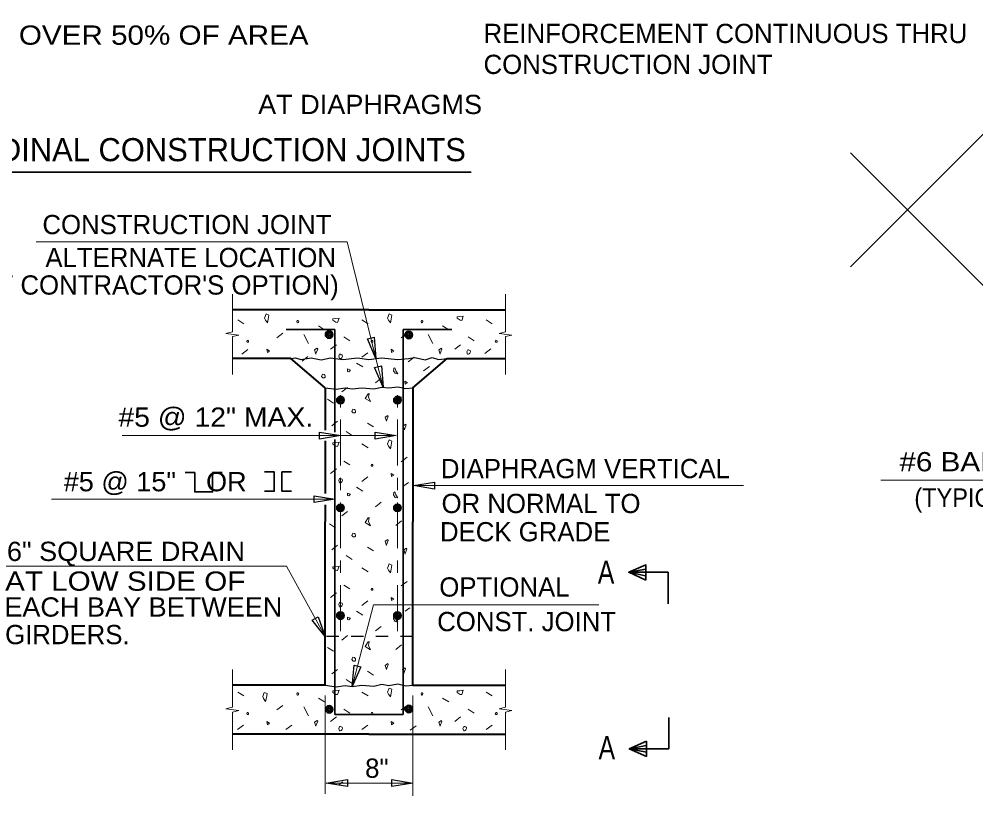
# Model space of a CAD drawing. Extents: x 0 to 34, y 0 to 23.4.
# Drawn here: x 16.45 to 24.21, y 9.27 to 15.58 of the extents above; entities that cross this region are included whole.
import ezdxf
from ezdxf.enums import TextEntityAlignment as Align

# ---------------------------------------------------------------- set-up
doc = ezdxf.new("R2010")
doc.units = 0
doc.header["$LTSCALE"] = 0.062
doc.linetypes.add('LONG_DASH_SHORT_DASH', pattern=[9.9, 6, -1.2, 1.5, -1.2])
doc.linetypes.add('SHORT_DASHED', pattern=[2.7, 1.5, -1.2])
for name, color, linetype, lineweight in [('1', 7, 'Continuous', 40), ('2', 7, 'SHORT_DASHED', 13), ('3', 7, 'Continuous', 35), ('4', 7, 'Continuous', 13), ('5', 7, 'LONG_DASH_SHORT_DASH', 13), ('7', 7, 'Continuous', 13)]:
    doc.layers.add(name, color=color, linetype=linetype, lineweight=lineweight)

msp = doc.modelspace()

# ---------------------------------------------------------------- linework, layer by layer
at = {"layer": '1', "lineweight": 13}
for p, q in [((18.1801, 13.03943), (18.1801, 13.34542)), ((20.39677, 13.03943), (20.39677, 13.34542)), ((18.1801, 12.69438), (18.1801, 13.00036)), ((20.39677, 12.69438), (20.39677, 13.00036)), ((18.1801, 9.99151), (18.1801, 10.2975)), ((20.39677, 9.99151), (20.39677, 10.2975)), ((18.1801, 9.64646), (18.1801, 9.95245)), ((20.39677, 9.64646), (20.39677, 9.95245))]:
    msp.add_line(p, q, dxfattribs=at)
at = {"layer": '1'}
for p, q in [((19.28844, 13.21781), (18.1801, 13.21781)), ((19.28844, 13.21781), (20.39677, 13.21781)), ((19.64469, 12.58448), (19.92177, 12.82198)), ((19.92177, 12.82198), (20.39677, 12.82198)), ((18.93219, 12.58448), (18.93219, 12.24099)), ((19.64469, 12.58448), (19.64469, 11.49594)), ((18.93219, 12.15427), (18.93219, 11.72719)), ((18.93219, 11.63474), (18.93219, 11.49594)), ((18.93219, 10.1699), (18.93219, 11.49594)), ((19.64469, 10.1699), (19.64469, 11.49594)), ((18.93219, 10.1699), (18.1801, 10.1699)), ((19.64469, 10.1699), (20.39677, 10.1699)), ((19.28844, 9.77406), (18.1801, 9.77406)), ((19.28844, 9.77406), (20.39677, 9.77406))]:
    msp.add_line(p, q, dxfattribs=at)
at = {"layer": '1', "lineweight": 13}
for points in [[(18.1801, 13.03943), (18.12802, 13.02641), (18.23219, 13.01339), (18.1801, 13.00036)], [(20.39677, 13.03943), (20.34469, 13.02641), (20.44885, 13.01339), (20.39677, 13.00036)], [(18.1801, 9.99151), (18.12802, 9.97849), (18.23219, 9.96547), (18.1801, 9.95245)], [(20.39677, 9.99151), (20.34469, 9.97849), (20.44885, 9.96547), (20.39677, 9.95245)]]:
    msp.add_lwpolyline(points, dxfattribs=at)
at = {"layer": '1'}
msp.add_lwpolyline([(18.93219, 12.58448), (18.6551, 12.82198), (18.1801, 12.82198)], dxfattribs=at)
at = {"layer": '1', "lineweight": 25}
for points in [[(18.6551, 12.82198), (18.69344, 12.82786), (18.73573, 12.81599), (18.81865, 12.82974), (18.90161, 12.81141), (18.97646, 12.82786), (19.07568, 12.81505), (19.19604, 12.82786), (19.28708, 12.81599), (19.3912, 12.8288), (19.52297, 12.81411), (19.60958, 12.82406), (19.6612, 12.83156), (19.74578, 12.81234), (19.80109, 12.83063), (19.85313, 12.81599), (19.92177, 12.82198)], [(18.93219, 12.58448), (19.02354, 12.57484), (19.09568, 12.58385), (19.15313, 12.57693), (19.23182, 12.58526), (19.32859, 12.5776), (19.39255, 12.59146), (19.45, 12.58385), (19.52214, 12.59427), (19.58776, 12.58036), (19.64469, 12.58448)], [(18.93219, 10.1699), (19.02354, 10.15849), (19.09568, 10.16917), (19.15313, 10.16094), (19.23182, 10.17078), (19.32859, 10.16177), (19.39255, 10.17818), (19.45, 10.16917), (19.52214, 10.18146), (19.58776, 10.16505), (19.64469, 10.1699)]]:
    msp.add_lwpolyline(points, dxfattribs=at)
at = {"layer": '2', "lineweight": 25}
msp.add_line((19.64469, 10.56573), (18.93219, 10.56573), dxfattribs=at)
at = {"layer": '3'}
for p, q in [((23.19479, 13.56807), (26.3226, 16.69589)), ((26.3226, 11.36385), (23.19479, 14.49167)), ((18.61552, 13.05948), (19.01135, 13.05948)), ((19.01135, 13.05948), (19.01135, 12.22406)), ((19.56552, 13.05948), (19.96135, 13.05948)), ((19.56552, 13.05948), (19.56552, 9.9324)), ((19.01135, 12.16604), (19.01135, 9.9324)), ((19.01135, 9.9324), (19.56552, 9.9324))]:
    msp.add_line(p, q, dxfattribs=at)
for points in [[(17.79656, 11.89714), (17.87531, 11.89714), (17.87531, 11.73953), (18.01974, 11.73953), (18.01974, 11.89714), (18.09854, 11.89714)], [(18.44172, 11.90266), (18.52047, 11.90266), (18.52047, 11.74505), (18.44172, 11.74505)], [(18.6612, 11.74505), (18.58245, 11.74505), (18.58245, 11.90266), (18.6612, 11.90266)]]:
    msp.add_lwpolyline(points, dxfattribs=at)
for centre, radius in [((18.96511, 13.01713), 0.03048), ((19.61092, 13.01431), 0.03048), ((18.96511, 13.01713), 0.02032), ((18.96511, 13.01713), 0.01016), ((19.61092, 13.01431), 0.02032), ((19.61092, 13.01431), 0.01016), ((19.0572, 12.4855), 0.03048), ((19.0572, 12.4855), 0.02032), ((19.51971, 12.48553), 0.03048), ((19.51971, 12.48553), 0.02032), ((19.0572, 12.4855), 0.01016), ((19.51971, 12.48553), 0.01016), ((19.05716, 11.61053), 0.03048), ((19.05716, 11.61053), 0.02032), ((19.05716, 11.61053), 0.01016), ((19.51971, 11.61053), 0.03048), ((19.51971, 11.61053), 0.02032), ((19.51971, 11.61053), 0.01016), ((19.05717, 10.7355), 0.03048), ((19.05717, 10.7355), 0.02032), ((19.05717, 10.7355), 0.01016), ((19.51969, 10.7355), 0.03048), ((19.51969, 10.7355), 0.02032), ((19.51969, 10.7355), 0.01016), ((18.96511, 9.97472), 0.03048), ((18.96511, 9.97472), 0.02032), ((18.96511, 9.97472), 0.01016), ((19.61092, 9.97754), 0.03048), ((19.61092, 9.97754), 0.02032), ((19.61092, 9.97754), 0.01016)]:
    msp.add_circle(centre, radius, dxfattribs=at)
at = {"layer": '4', "lineweight": 35}
for p, q in [((15.0951, 14.3362), (20.11854, 14.3362)), ((21.39667, 11.08708), (21.53594, 11.11286)), ((21.39667, 11.08708), (21.53297, 11.05745)), ((21.71667, 11.08708), (21.71667, 10.83109)), ((21.72052, 9.65281), (21.72052, 9.9088)), ((21.40052, 9.65281), (21.53682, 9.68245)), ((21.40052, 9.65281), (21.53979, 9.62703))]:
    msp.add_line(p, q, dxfattribs=at)
at = {"layer": '4'}
for p, q in [((16.58875, 13.77057), (19.11203, 13.77057)), ((19.11203, 13.77057), (19.34531, 12.82318)), ((19.34531, 12.82318), (19.40271, 12.5901)), ((17.28469, 12.19688), (19.05891, 12.19688)), ((19.05891, 12.19688), (19.50948, 12.19688)), ((19.43802, 12.20599), (19.45922, 12.18833)), ((19.65031, 11.79109), (22.32781, 11.79109)), ((16.71297, 11.68135), (19.01135, 11.68135)), ((19.32406, 10.82224), (19.15182, 10.16115)), ((19.32406, 10.82224), (21.1538, 10.82224)), ((18.93219, 10.0863), (18.93219, 9.28776)), ((19.64469, 10.0863), (19.64469, 9.27219)), ((18.94208, 9.37641), (19.64469, 9.37641)), ((19.07594, 9.38693), (19.04057, 9.35865))]:
    msp.add_line(p, q, dxfattribs=at)
at = {"layer": '4', "lineweight": 25}
for points in [[(19.27547, 12.98333), (19.33078, 12.99698), (19.34401, 12.82411)], [(19.33417, 12.74932), (19.38948, 12.76297), (19.40271, 12.5901)], [(18.88792, 12.16839), (18.88792, 12.22536), (19.05891, 12.19688)], [(19.33849, 12.16839), (19.33849, 12.22536), (19.50948, 12.19688)], [(19.8213, 11.81958), (19.8213, 11.7626), (19.65031, 11.79109)], [(18.84438, 11.65354), (18.84438, 11.70917), (19.01135, 11.68135)], [(18.82771, 10.69891), (18.87656, 10.72563), (18.93219, 10.56573)], [(19.16734, 10.3338), (19.22255, 10.31943), (19.15182, 10.16115)], [(19.11307, 9.4049), (19.11307, 9.34792), (18.94208, 9.37641)], [(19.4737, 9.34792), (19.4737, 9.4049), (19.64469, 9.37641)]]:
    msp.add_lwpolyline(points, close=True, dxfattribs=at)
at = {"layer": '4'}
for points in [[(14.30089, 12.47807), (16.32745, 11.13833), (18.61932, 11.13833), (18.93219, 10.56573)], [(23.44297, 11.83401), (25.27693, 11.83401), (25.55833, 12.11911)]]:
    msp.add_lwpolyline(points, dxfattribs=at)
at = {"layer": '4', "lineweight": 35}
for points in [[(21.39667, 11.08708), (21.53526, 11.14719), (21.53526, 11.02307)], [(21.71667, 11.08708), (21.39667, 11.08708), (21.53526, 11.02307)], [(21.72052, 9.65281), (21.40052, 9.65281), (21.53911, 9.71682)], [(21.40052, 9.65281), (21.53911, 9.59271), (21.53911, 9.71682)]]:
    msp.add_lwpolyline(points, dxfattribs=at)
at = {"layer": '5'}
for p, q in [((19.05719, 10.61052), (19.05719, 12.56885)), ((19.51969, 10.61052), (19.51969, 12.56885))]:
    msp.add_line(p, q, dxfattribs=at)
at = {"layer": '7'}
for p, q in [((18.22323, 13.13714), (18.27266, 13.10583)), ((19.23161, 13.13714), (19.28104, 13.10583)), ((20.24, 13.13714), (20.28943, 13.10583)), ((18.87792, 13.08807), (18.9274, 13.05682)), ((19.8863, 13.08807), (19.93578, 13.05682)), ((18.58885, 13.02839), (18.54073, 12.99177)), ((18.76042, 13.01729), (18.79708, 12.94375)), ((19.08427, 12.99776), (19.13375, 12.96651)), ((19.59724, 13.02839), (19.54911, 12.99177)), ((19.7688, 13.01729), (19.80547, 12.94375)), ((20.09266, 12.99776), (20.14214, 12.96651)), ((18.30599, 12.89531), (18.25786, 12.8587)), ((19.0238, 12.93464), (18.97568, 12.89802)), ((20.03219, 12.93464), (19.98406, 12.89802)), ((20.27656, 12.90042), (20.22844, 12.8638)), ((18.79359, 12.8388), (18.74547, 12.80219)), ((19.27844, 12.86964), (19.23031, 12.83302)), ((19.65557, 12.83271), (19.60745, 12.79609)), ((19.18849, 12.78568), (19.23797, 12.75443)), ((19.77984, 12.75875), (19.73172, 12.72214)), ((19.38875, 12.66318), (19.34063, 12.62656)), ((19.11521, 12.58849), (19.06708, 12.55188)), ((19.5538, 12.51203), (19.50568, 12.47542)), ((18.95219, 12.4924), (19.00172, 12.4612)), ((19.03411, 12.31375), (18.98599, 12.27714)), ((19.27656, 12.2988), (19.32599, 12.26776)), ((19.10302, 12.23052), (19.15255, 12.19927)), ((19.23161, 12.12979), (19.28104, 12.09849)), ((19.08427, 11.99042), (19.13375, 11.95917)), ((19.59724, 12.02104), (19.54911, 11.98443)), ((19.0238, 11.92729), (18.97568, 11.89068)), ((19.27844, 11.86229), (19.23031, 11.82568)), ((19.6088, 11.81708), (19.57156, 11.78875)), ((19.18849, 11.77833), (19.23797, 11.74708)), ((19.38875, 11.65583), (19.34063, 11.61922)), ((19.11521, 11.58115), (19.06708, 11.54453)), ((19.5538, 11.50469), (19.50568, 11.46807)), ((18.96755, 11.4799), (19.01708, 11.4487)), ((19.03411, 11.30641), (18.98599, 11.26979)), ((19.27656, 11.29146), (19.32599, 11.26042)), ((19.10302, 11.22318), (19.15255, 11.19193)), ((19.23161, 11.12245), (19.28104, 11.09115)), ((19.08427, 10.98307), (19.13375, 10.95182)), ((19.59724, 11.0137), (19.54911, 10.97708)), ((19.0238, 10.91995), (18.97568, 10.88333)), ((19.27844, 10.85495), (19.23031, 10.81833)), ((19.61901, 10.79943), (19.58177, 10.77109)), ((19.18849, 10.77099), (19.23797, 10.73974)), ((19.38875, 10.64849), (19.34063, 10.61188)), ((19.11521, 10.5738), (19.06708, 10.53719)), ((19.5538, 10.49734), (19.50568, 10.46073)), ((18.95219, 10.47771), (19.00172, 10.44651)), ((19.03411, 10.29906), (18.98599, 10.26245)), ((19.27656, 10.28411), (19.32599, 10.25307)), ((19.10302, 10.21583), (19.15255, 10.18458)), ((18.22323, 10.1151), (18.27266, 10.0838)), ((19.23161, 10.1151), (19.28104, 10.0838)), ((20.24, 10.1151), (20.28943, 10.0838)), ((18.87792, 10.06604), (18.9274, 10.03479)), ((19.8863, 10.06604), (19.93578, 10.03479)), ((18.58885, 10.00635), (18.54073, 9.96974)), ((18.76042, 9.99526), (18.79708, 9.92172)), ((19.08427, 9.97573), (19.13375, 9.94448)), ((19.59724, 10.00635), (19.54911, 9.96974)), ((19.7688, 9.99526), (19.80547, 9.92172)), ((20.09266, 9.97573), (20.14214, 9.94448)), ((19.0238, 9.9126), (18.97568, 9.87599)), ((20.03219, 9.9126), (19.98406, 9.87599)), ((18.27005, 9.8476), (18.22193, 9.81099)), ((18.6626, 9.84661), (18.61448, 9.81)), ((19.27844, 9.8476), (19.23031, 9.81099)), ((19.67099, 9.84151), (19.62286, 9.8049)), ((20.28682, 9.8476), (20.2387, 9.81099))]:
    msp.add_line(p, q, dxfattribs=at)
for points in [[(18.45328, 13.18495), (18.44208, 13.15182), (18.44776, 13.13526), (18.46432, 13.11313), (18.47167, 13.1426), (18.47719, 13.17578)], [(18.70344, 13.12229), (18.70635, 13.11307), (18.70901, 13.11307), (18.71276, 13.11401), (18.71547, 13.11667), (18.71813, 13.12229), (18.7174, 13.12781), (18.71276, 13.12875), (18.71078, 13.13068), (18.70714, 13.13068)], [(19.01766, 13.1476), (18.99557, 13.14573), (18.99557, 13.13469), (19.01953, 13.11818), (19.0325, 13.1163), (19.04542, 13.15125)], [(19.45141, 13.1849), (19.44021, 13.15177), (19.44589, 13.13521), (19.46245, 13.11307), (19.46979, 13.14255), (19.47531, 13.17573)], [(19.71182, 13.12229), (19.71474, 13.11307), (19.7174, 13.11307), (19.72115, 13.11401), (19.72385, 13.11667), (19.72651, 13.12229), (19.72578, 13.12781), (19.72115, 13.12875), (19.71917, 13.13068), (19.71552, 13.13068)], [(20.02604, 13.16302), (20.00396, 13.16115), (20.00396, 13.1501), (20.02792, 13.13359), (20.04089, 13.13172), (20.0538, 13.16667)], [(18.30151, 12.97167), (18.29688, 12.96151), (18.30229, 12.95589), (18.30891, 12.95589), (18.31161, 12.95885), (18.31161, 12.96427), (18.31073, 12.96693), (18.30786, 12.9699)], [(19.3099, 12.97167), (19.30526, 12.96151), (19.31068, 12.95589), (19.31729, 12.95589), (19.32, 12.95885), (19.32, 12.96427), (19.31911, 12.96693), (19.31625, 12.9699)], [(20.31828, 12.97167), (20.31365, 12.96151), (20.31906, 12.95589), (20.32568, 12.95589), (20.32839, 12.95885), (20.32839, 12.96427), (20.3275, 12.96693), (20.32464, 12.9699)], [(18.46042, 12.89792), (18.46411, 12.87208), (18.4826, 12.88318)], [(18.84646, 12.8925), (18.85786, 12.85927), (18.85786, 12.86286), (18.87255, 12.89984), (18.8688, 12.90719)], [(19.4688, 12.89792), (19.4725, 12.87208), (19.49099, 12.88318)], [(19.85484, 12.8925), (19.86625, 12.85927), (19.86625, 12.86286), (19.88094, 12.89984), (19.87719, 12.90719)], [(20.08224, 12.87672), (20.08807, 12.85828), (20.09339, 12.85828), (20.10089, 12.8601), (20.1063, 12.86547), (20.11167, 12.87672), (20.11016, 12.88766), (20.10089, 12.88958), (20.09698, 12.89339), (20.08964, 12.89339)], [(19.04307, 12.84078), (19.04891, 12.82234), (19.05422, 12.82234), (19.06172, 12.82417), (19.06714, 12.82953), (19.0725, 12.84078), (19.07099, 12.85172), (19.06172, 12.85365), (19.05781, 12.85745), (19.05047, 12.85745)], [(19.11479, 12.73833), (19.11391, 12.71854), (19.12583, 12.71578), (19.13734, 12.72911)], [(19.49125, 12.7438), (19.48719, 12.72307), (19.50094, 12.70276), (19.52396, 12.69823), (19.50557, 12.7226), (19.49771, 12.74792)], [(18.91182, 12.69672), (18.90255, 12.67651), (18.91339, 12.66526), (18.92661, 12.66526), (18.93203, 12.67115), (18.93203, 12.68193), (18.93021, 12.68724), (18.92448, 12.69318)], [(19.57896, 12.63964), (19.58266, 12.6138), (19.60115, 12.6249)], [(19.28214, 12.53745), (19.25641, 12.49891), (19.29969, 12.47297), (19.28391, 12.50802), (19.29057, 12.5401)], [(19.15786, 12.41297), (19.14859, 12.39276), (19.15943, 12.38151), (19.17266, 12.38151), (19.17807, 12.3874), (19.17807, 12.39818), (19.17625, 12.40349), (19.17052, 12.40943)], [(19.41906, 12.34656), (19.43042, 12.31333), (19.43042, 12.31688), (19.44521, 12.35391), (19.44146, 12.36125)], [(19.56505, 12.27583), (19.57646, 12.24266), (19.57646, 12.2462), (19.59115, 12.28323), (19.5874, 12.29057)], [(19.01766, 12.14026), (18.99557, 12.13839), (18.99557, 12.12734), (19.01953, 12.11083), (19.0325, 12.10896), (19.04542, 12.14391)], [(19.45141, 12.16219), (19.44021, 12.12906), (19.44589, 12.1125), (19.46245, 12.09036), (19.46979, 12.11984), (19.47531, 12.15302)], [(19.3099, 11.96432), (19.30526, 11.95417), (19.31068, 11.94854), (19.31729, 11.94854), (19.32, 11.95151), (19.32, 11.95693), (19.31911, 11.95958), (19.31625, 11.96255)], [(19.4688, 11.89057), (19.4725, 11.86474), (19.49099, 11.87583)], [(19.04307, 11.83344), (19.04891, 11.815), (19.05422, 11.815), (19.06172, 11.81682), (19.06714, 11.82219), (19.0725, 11.83344), (19.07099, 11.84438), (19.06172, 11.8463), (19.05781, 11.8501), (19.05047, 11.8501)], [(19.11479, 11.73099), (19.11391, 11.7112), (19.12583, 11.70844), (19.13734, 11.72177)], [(19.49125, 11.73646), (19.48719, 11.71573), (19.50094, 11.69542), (19.52396, 11.69089), (19.50557, 11.71526), (19.49771, 11.74057)], [(19.28214, 11.5301), (19.25641, 11.49156), (19.29969, 11.46563), (19.28391, 11.50068), (19.29057, 11.53276)], [(19.15786, 11.40563), (19.14859, 11.38542), (19.15943, 11.37417), (19.17266, 11.37417), (19.17807, 11.38005), (19.17807, 11.39083), (19.17625, 11.39615), (19.17052, 11.40208)], [(19.41906, 11.33922), (19.43042, 11.30599), (19.43042, 11.30953), (19.44521, 11.34656), (19.44146, 11.35391)], [(19.57021, 11.26849), (19.58161, 11.23531), (19.58161, 11.23885), (19.5963, 11.27589), (19.59255, 11.28323)], [(19.01766, 11.13292), (18.99557, 11.13104), (18.99557, 11.12), (19.01953, 11.10349), (19.0325, 11.10161), (19.04542, 11.13656)], [(19.45141, 11.15484), (19.44021, 11.12172), (19.44589, 11.10516), (19.46245, 11.08302), (19.46979, 11.1125), (19.47531, 11.14568)], [(19.3099, 10.95698), (19.30526, 10.94682), (19.31068, 10.9412), (19.31729, 10.9412), (19.32, 10.94417), (19.32, 10.94958), (19.31911, 10.95224), (19.31625, 10.95521)], [(19.4688, 10.88323), (19.4725, 10.8574), (19.49099, 10.86849)], [(19.04307, 10.82609), (19.04891, 10.80766), (19.05422, 10.80766), (19.06172, 10.80948), (19.06714, 10.81484), (19.0725, 10.82609), (19.07099, 10.83703), (19.06172, 10.83896), (19.05781, 10.84276), (19.05047, 10.84276)], [(19.11479, 10.72365), (19.11391, 10.70385), (19.12583, 10.70109), (19.13734, 10.71443)], [(19.49125, 10.72911), (19.48719, 10.70839), (19.50094, 10.68807), (19.52396, 10.68354), (19.50557, 10.70792), (19.49771, 10.73323)], [(19.28214, 10.52276), (19.25641, 10.48422), (19.29969, 10.45828), (19.28391, 10.49333), (19.29057, 10.52542)], [(19.15786, 10.39828), (19.14859, 10.37807), (19.15943, 10.36682), (19.17266, 10.36682), (19.17807, 10.37271), (19.17807, 10.38349), (19.17625, 10.3888), (19.17052, 10.39474)], [(19.41906, 10.33188), (19.43042, 10.29865), (19.43042, 10.30219), (19.44521, 10.33922), (19.44146, 10.34656)], [(19.5599, 10.29708), (19.5713, 10.26391), (19.5713, 10.26745), (19.58599, 10.30448), (19.58224, 10.31182)], [(18.43792, 10.11156), (18.42672, 10.07844), (18.4324, 10.06188), (18.44896, 10.03974), (18.4563, 10.06922), (18.46182, 10.1024)], [(18.70344, 10.10026), (18.70635, 10.09104), (18.70901, 10.09104), (18.71276, 10.09198), (18.71547, 10.09464), (18.71813, 10.10026), (18.7174, 10.10578), (18.71276, 10.10672), (18.71078, 10.10865), (18.70714, 10.10865)], [(19.01766, 10.12557), (18.99557, 10.1237), (18.99557, 10.11266), (19.01953, 10.09615), (19.0325, 10.09427), (19.04542, 10.12922)], [(19.45141, 10.1475), (19.44021, 10.11438), (19.44589, 10.09781), (19.46245, 10.07568), (19.46979, 10.10516), (19.47531, 10.13833)], [(19.71182, 10.10026), (19.71474, 10.09104), (19.7174, 10.09104), (19.72115, 10.09198), (19.72385, 10.09464), (19.72651, 10.10026), (19.72578, 10.10578), (19.72115, 10.10672), (19.71917, 10.10865), (19.71552, 10.10865)], [(20.02604, 10.12557), (20.00396, 10.1237), (20.00396, 10.11266), (20.02792, 10.09615), (20.04089, 10.09427), (20.0538, 10.12922)], [(18.30151, 9.94964), (18.29688, 9.93948), (18.30229, 9.93385), (18.30891, 9.93385), (18.31161, 9.93682), (18.31161, 9.94224), (18.31073, 9.9449), (18.30786, 9.94786)], [(19.3099, 9.94964), (19.30526, 9.93948), (19.31068, 9.93385), (19.31729, 9.93385), (19.32, 9.93682), (19.32, 9.94224), (19.31911, 9.9449), (19.31625, 9.94786)], [(20.31828, 9.94964), (20.31365, 9.93948), (20.31906, 9.93385), (20.32568, 9.93385), (20.32839, 9.93682), (20.32839, 9.94224), (20.3275, 9.9449), (20.32464, 9.94786)], [(18.46042, 9.87589), (18.46411, 9.85005), (18.4826, 9.86115)], [(18.84646, 9.87047), (18.85786, 9.83724), (18.85786, 9.84083), (18.87255, 9.87781), (18.8688, 9.88516)], [(19.4688, 9.87589), (19.4725, 9.85005), (19.49099, 9.86115)], [(19.85484, 9.87047), (19.86625, 9.83724), (19.86625, 9.84083), (19.88094, 9.87781), (19.87719, 9.88516)], [(19.04307, 9.81875), (19.04891, 9.80031), (19.05422, 9.80031), (19.06172, 9.80214), (19.06714, 9.8075), (19.0725, 9.81875), (19.07099, 9.82969), (19.06172, 9.83161), (19.05781, 9.83542), (19.05047, 9.83542)], [(20.05146, 9.81875), (20.05729, 9.80031), (20.0626, 9.80031), (20.0701, 9.80214), (20.07552, 9.8075), (20.08089, 9.81875), (20.07938, 9.82969), (20.0701, 9.83161), (20.0662, 9.83542), (20.05885, 9.83542)]]:
    msp.add_lwpolyline(points, close=True, dxfattribs=at)

# ---------------------------------------------------------------- texts
at = {"layer": '4'}
for s, width, p in [('OVER 50% OF AREA', 1.15, (17.62318, 15.37047)), ('AT DIAPHRAGMS', 1.05, (19.29797, 14.8076))]:
    msp.add_text(s, height=0.1563, dxfattribs=dict(at, width=width)).set_placement(p, align=Align.CENTER)
for s, p in [('REINFORCEMENT CONTINUOUS THRU', (20.21833, 15.38401)), ('CONSTRUCTION JOINT', (20.21833, 15.13297)), ('DIAPHRAGM VERTICAL', (19.87182, 11.85141)), ('OR NORMAL TO', (19.87755, 11.56823)), ('DECK GRADE', (19.86479, 11.33865)), ('OPTIONAL ', (19.85932, 10.89)), ('CONST. JOINT', (19.84214, 10.60927)), ('GIRDERS.', (16.33599, 10.50375))]:
    msp.add_text(s, height=0.1563, dxfattribs=at).set_placement(p)
for s, height, p in [('LONGITUDINAL CONSTRUCTION JOINTS', 0.1875, (17.62299, 14.42484)), ('8"', 0.1563, (19.35258, 9.41911))]:
    msp.add_text(s, height=height, dxfattribs=at).set_placement(p, align=Align.CENTER)
for s, p in [('CONSTRUCTION JOINT', (18.98438, 13.83255)), ('ALTERNATE LOCATION', (19.02073, 13.56484)), ("(AT CONTRACTOR'S OPTION)", (19.04349, 13.34182))]:
    msp.add_text(s, height=0.1563, dxfattribs=at).set_placement(p, align=Align.RIGHT)
for s, height, width, p in [('#5 @ 12" MAX.', 0.1563, 1.1, (17.25568, 12.26901)), ('#5 @ 15"    OR', 0.1563, 1.05, (16.81182, 11.74516)), ('(TYPICAL)', 0.1504, 0.95, (23.71359, 11.61792)), ('6" SQUARE DRAIN', 0.1563, 1.05, (16.35104, 11.17911)), ('AT LOW SIDE OF', 0.1563, 1.15, (16.33599, 10.9376)), ('EACH BAY BETWEEN', 0.1563, 1.05, (16.32964, 10.7275))]:
    msp.add_text(s, height=height, dxfattribs=dict(at, width=width)).set_placement(p)
for s, height, width, p in [('#6 BARS x 6\'-0"', 0.1563, 1.15, (25.3138, 11.90719)), ('A', 0.1875, 0.8, (21.27927, 10.99552)), ('A', 0.1875, 0.8, (21.28547, 9.56979))]:
    msp.add_text(s, height=height, dxfattribs=dict(at, width=width)).set_placement(p, align=Align.RIGHT)

doc.saveas('drawing.dxf')
